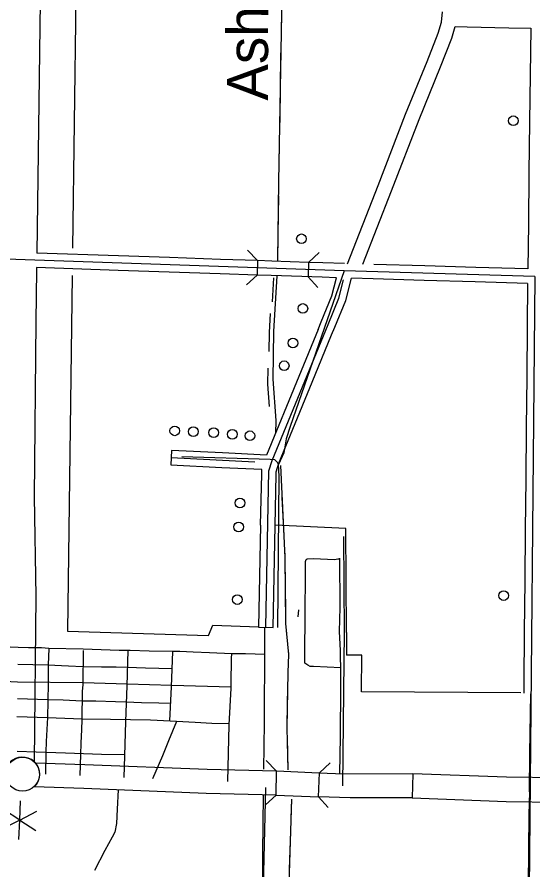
# Model space of a CAD drawing. Extents: x -4306 to 3843, y 131 to 8053.
# Drawn here: x 589 to 1443, y 3441 to 4853 of the extents above; entities that cross this region are included whole.
import ezdxf

# ---------------------------------------------------------------- set-up
doc = ezdxf.new("R2010")
doc.units = 0
for name, color, linetype in [('10', 7, 'Continuous'), ('24', 7, 'Continuous'), ('31', 7, 'Continuous'), ('32', 7, 'Continuous'), ('33', 7, 'Continuous'), ('34', 7, 'Continuous'), ('37', 7, 'Continuous'), ('38', 7, 'Continuous'), ('43', 7, 'Continuous'), ('46', 7, 'Continuous'), ('48', 7, 'Continuous'), ('56', 7, 'Continuous'), ('6', 7, 'Continuous')]:
    doc.layers.add(name, color=color, linetype=linetype)

msp = doc.modelspace()

# ---------------------------------------------------------------- linework, layer by layer
at = {"layer": '10'}
for p, q in [((1018.3, 3604.8), (1017.4, 3564.8)), ((1018.8, 3604.8), (1019.4, 3604.8)), ((1019.4, 3604.8), (1088.9, 3601.8)), ((1088.1, 3561.8), (1089.8, 3601.7)), ((1244.5, 3599.9), (1243, 3559.9)), ((1244.5, 3599.9), (1243, 3559.9)), ((1018.2, 3564.8), (1087.9, 3561.8))]:
    msp.add_line(p, q, dxfattribs=at)
for points in [[(968.7, 5290.2), (692.8, 5302.6), (674.8, 5297.7), (651, 5282.1), (641.1, 5271.4), (634.9, 5260.6), (632.5, 5254), (621.8, 4462.2)], [(621.5, 4438.2), (621.4, 4434.2)], [(621.4, 4434.2), (620.3, 4349.1), (617.7, 4058.9)], [(617.7, 4058.9), (620.3, 3894), (617.5, 3620.2)], [(619.7, 3618.1), (701.5, 3615.5), (903.8, 3607.5), (1018.5, 3604.8)], [(1088.9, 3601.8), (1116.1, 3600.6)], [(1116.1, 3600.6), (1244.5, 3599.9)], [(1819.6, 3589.7), (1570.2, 3591.9), (1399.5, 3594.1), (1244.5, 3599.9)], [(1018.2, 3564.8), (1018.1, 3564.8), (902.5, 3567.5), (700, 3575.5), (617.3, 3578.2)], [(1140.7, 3560), (1087.9, 3561.8)], [(1243, 3559.9), (1140.7, 3560)], [(1243, 3559.9), (1398.5, 3554.1), (1569.7, 3551.9), (1817.9, 3549.8)]]:
    msp.add_lwpolyline(points, dxfattribs=at)
for centre, radius, start, end in [((598.1, 3598.2), 29.3, 48.5826, 134.7506), ((598.5, 3599.3), 28.3, 311.6906, 41.5462)]:
    msp.add_arc(centre, radius, start, end, dxfattribs=at)
at = {"layer": '24'}
msp.add_circle((598.4, 3599.4), 28, dxfattribs=at)
at = {"layer": '31'}
for p, q in [((1110.5, 4391.4), (1118.2, 4421.4)), ((1121.9, 4387.6), (1129.7, 4418)), ((1133.3, 4383.8), (1142.8, 4420.7)), ((1092.8, 4348.6), (1110.5, 4391.4)), ((1103.9, 4344), (1121.9, 4387.6)), ((1115, 4339.4), (1133.3, 4383.8)), ((1011.3, 4118.6), (1103.9, 4344)), ((1087.6, 4336), (1092.8, 4348.6)), ((1109.8, 4326.9), (1115, 4339.4)), ((1087.6, 4336), (1087.6, 4336)), ((1022.6, 4114.6), (1045.6, 4170.6)), ((844.7, 4135.6), (843.5, 4111.6)), ((844.1, 4123.6), (982.6, 4116.8)), ((1006.2, 4101.9), (1011.3, 4118.6)), ((1018.2, 4100), (1022.6, 4114.6)), ((994.1, 4096.2), (994.2, 4103.8)), ((1001, 3842.6), (1006.2, 4101.9)), ((1018.1, 4095.7), (1018.2, 4100)), ((992.4, 4011.8), (994.1, 4096.2)), ((1016.4, 4011.3), (1018.1, 4095.7)), ((1054.8, 3871.6), (1054, 3859.8)), ((989, 3842.8), (1012.9, 3842.3))]:
    msp.add_line(p, q, dxfattribs=at)
for points in [[(1087.6, 4336), (1055.5, 4257.9)], [(1077.7, 4248.7), (1109.8, 4326.9)], [(1055.5, 4257.9), (1002.1, 4127.9)], [(1045.6, 4170.6), (1077.7, 4248.7)], [(929.1, 4131.5), (844.7, 4135.6)], [(1002.1, 4127.9), (929.1, 4131.5)], [(843.5, 4111.6), (927.9, 4107.5)], [(927.9, 4107.5), (994.3, 4104.3)], [(992.4, 4011.8), (990.7, 3927.3)], [(1014.7, 3926.8), (1016.4, 4011.3)], [(990.7, 3927.3), (989, 3842.8)], [(1012.9, 3842.3), (1014.7, 3926.8)]]:
    msp.add_lwpolyline(points, dxfattribs=at)
at = {"layer": '32'}
for p, q in [((1439.6, 4834.8), (1437.6, 4679.9)), ((1437.6, 4679.9), (1436.5, 4595.5)), ((1436.5, 4595.5), (1435.5, 4511)), ((1435.5, 4511), (1434.5, 4436.2)), ((602.5, 4450.9), (-239.3, 4486.5)), ((1130.8, 4433), (602.5, 4450.9)), ((757.3, 4457.6), (621.8, 4462.2)), ((841.8, 4454.8), (757.3, 4457.6)), ((926.2, 4451.9), (841.8, 4454.8)), ((987.3, 4449.9), (926.2, 4451.9)), ((987.3, 4449.9), (986.5, 4425.9)), ((1010.7, 4449.1), (987.3, 4449.9)), ((756.5, 4433.6), (621.5, 4438.2)), ((1071.7, 4447), (1010.7, 4449.1)), ((1071.8, 4447), (1071, 4423)), ((1095.1, 4446.2), (1071.8, 4447)), ((1131.2, 4445), (1095.1, 4446.2)), ((1263.9, 4441.1), (1179.5, 4443.6)), ((1348.4, 4438.7), (1263.9, 4441.1)), ((1434.5, 4436.2), (1348.4, 4438.7)), ((841, 4430.8), (756.5, 4433.6)), ((925.4, 4427.9), (841, 4430.8)), ((986.5, 4425.9), (925.4, 4427.9)), ((1009.9, 4425.1), (986.5, 4425.9)), ((1094.3, 4422.2), (1009.9, 4425.1)), ((1130.8, 4433), (1041.4, 4175.2)), ((1118.2, 4421.4), (1094.3, 4422.2)), ((1446.4, 4423.8), (1130.8, 4433)), ((1446.4, 4423.8), (1434.2, 3147)), ((1178.8, 4419.6), (1142.8, 4420.7)), ((1263.2, 4417.1), (1178.8, 4419.6)), ((1347.7, 4414.7), (1263.2, 4417.1)), ((1434.2, 4412.2), (1347.7, 4414.7)), ((1434.2, 4412.2), (1433.6, 4342)), ((1433.6, 4342), (1432.8, 4257.5)), ((1432.8, 4257.5), (1432, 4173)), ((1041.4, 4175.2), (1034.5, 4154.8)), ((1432, 4173), (1431.2, 4088.5)), ((1034.5, 4154.8), (1030.7, 4131.6)), ((1007.9, 4120.3), (862, 4124.7)), ((1030.7, 4131.6), (1021.8, 4112.2)), ((1016.1, 4120.1), (1007.9, 4120.3)), ((1020.2, 4115.4), (1016.1, 4120.1)), ((1021.8, 4112.2), (1020.2, 4115.4)), ((1023.3, 4093), (1021.8, 4112.2)), ((1020.6, 3842.1), (1023.3, 4093)), ((1431.2, 4088.5), (1430.4, 4004)), ((1430.4, 4004), (1429.5, 3919.5)), ((1429.5, 3919.5), (1428.7, 3835.1)), ((1428.7, 3835.1), (1427.9, 3750.6)), ((1427.9, 3750.6), (1427.8, 3733.7))]:
    msp.add_line(p, q, dxfattribs=at)
for points in [[(1129.5, 3992.9), (1130.7, 3833.8)], [(1130.7, 3833.8), (1129.6, 3736.4), (1127.8, 3580.1)], [(929.3, 3181.4), (991.6, 3178), (1001, 3577.3)]]:
    msp.add_lwpolyline(points, dxfattribs=at)
at = {"layer": '33'}
for p, q in [((1067.6, 3954.6), (1069.6, 3956)), ((1069.6, 3956), (1079.9, 3956.3)), ((1079.9, 3956.3), (1114.5, 3955)), ((1114.5, 3955), (1120.1, 3955.7)), ((1120.1, 3955.7), (1122.8, 3956)), ((1123.8, 3875.3), (1123.7, 3956.8)), ((1066.7, 3951.8), (1067.6, 3954.6)), ((1066.7, 3936.2), (1066.7, 3951.8)), ((1065.9, 3858.9), (1066.7, 3936.2)), ((1123, 3835.6), (1123.8, 3875.3)), ((1065.5, 3803), (1065.9, 3858.9)), ((999.4, 3775.4), (999.4, 3841.3)), ((1124.5, 3804.4), (1123, 3835.6)), ((591.3, 3809), (564.4, 3810.1)), ((608.1, 3808.4), (591.3, 3809)), ((629.5, 3808.6), (608.1, 3808.4)), ((641.7, 3807.3), (629.5, 3808.6)), ((641.7, 3807.3), (640.5, 3780.5)), ((698.5, 3806.3), (641.7, 3807.3)), ((698.4, 3747.7), (699.2, 3804)), ((758.3, 3804.4), (698.5, 3806.3)), ((773.3, 3803.9), (758.3, 3804.4)), ((771.6, 3745.4), (773.2, 3803.9)), ((776.7, 3804.2), (773.3, 3803.9)), ((808, 3803), (776.7, 3804.2)), ((846.2, 3802.4), (808, 3803)), ((845.1, 3743.7), (846.8, 3802.4)), ((858.4, 3802.3), (846.2, 3802.4)), ((880.5, 3801.2), (858.4, 3802.3)), ((907.5, 3800.1), (880.5, 3801.2)), ((944.9, 3798.8), (907.5, 3800.1)), ((1065.4, 3787.9), (1065.5, 3803)), ((1125.1, 3765.2), (1124.5, 3804.4)), ((943.7, 3748.7), (944.4, 3791.5)), ((944.4, 3791.5), (944.9, 3798.8)), ((967.4, 3798.5), (944.9, 3798.8)), ((999.4, 3797.7), (967.4, 3798.5)), ((1065.8, 3783.4), (1065.4, 3787.9)), ((590.7, 3781.3), (640.4, 3780.2)), ((640.4, 3780.2), (674.2, 3778.6)), ((640.5, 3780.5), (640.5, 3749.5)), ((674.2, 3778.6), (698.3, 3777.9)), ((698.3, 3777.9), (729.2, 3777)), ((729.2, 3777), (753.3, 3777.3)), ((753.3, 3777.3), (771.9, 3776.4)), ((771.9, 3776.4), (801.7, 3775.4)), ((801.7, 3775.4), (845.9, 3774.1)), ((999.4, 3758.1), (999.4, 3775.4)), ((1070.5, 3779.6), (1065.8, 3783.4)), ((1074.5, 3777.5), (1070.5, 3779.6)), ((1079.9, 3777.5), (1074.5, 3777.5)), ((1125, 3775.7), (1079.9, 3777.5)), ((999, 3738.5), (999.4, 3758.1)), ((1125.1, 3743.4), (1125.1, 3765.2)), ((590.2, 3751.8), (520, 3754.9)), ((698.6, 3750.7), (590.2, 3751.8)), ((640.5, 3749.5), (640.4, 3720.9)), ((697.3, 3736.3), (698.4, 3747.7)), ((771.7, 3748.3), (698.6, 3750.7)), ((769.4, 3686.8), (771.6, 3745.4)), ((845.2, 3746.1), (771.7, 3748.3)), ((842.2, 3687.8), (845.1, 3743.7)), ((943.6, 3743.5), (845.2, 3746.1)), ((943.6, 3741.6), (943.7, 3748.7)), ((1124.3, 3661.2), (1125.1, 3743.4)), ((696.9, 3689.1), (697.3, 3736.3)), ((940.3, 3681.3), (943.6, 3741.6)), ((999, 3722.6), (999, 3738.5)), ((1438.2, 3634.3), (1439.7, 3732.3)), ((589.9, 3724.6), (639.9, 3723.1)), ((640.4, 3720.9), (639.6, 3693.2)), ((639.9, 3723.1), (665.4, 3722.3)), ((665.4, 3722.3), (697, 3720.9)), ((697, 3720.9), (719.8, 3720.6)), ((719.8, 3720.6), (752.1, 3719.8)), ((752.1, 3719.8), (770, 3719.1)), ((770, 3719.1), (795.3, 3718.3)), ((795.3, 3718.3), (823.9, 3717.6)), ((823.9, 3717.6), (843.3, 3716.9)), ((998.9, 3685), (999, 3722.6)), ((589, 3694.9), (639.6, 3693.2)), ((639.6, 3693.2), (637.4, 3653.5)), ((639.6, 3693.2), (696.8, 3691.2)), ((696.5, 3673.5), (696.9, 3689.1)), ((696.8, 3691.2), (743.9, 3690.3)), ((743.9, 3690.3), (809.9, 3689.1)), ((767.8, 3629.6), (769.4, 3686.8)), ((809.9, 3689.1), (842.5, 3687.8)), ((840.6, 3655), (853.8, 3687.2)), ((842.5, 3687.8), (852.9, 3687.3)), ((852.9, 3687.3), (883.8, 3685.2)), ((695.1, 3650.8), (696.5, 3673.5)), ((883.8, 3685.2), (911.5, 3683.8)), ((911.5, 3683.8), (939.8, 3683)), ((938.1, 3587.4), (940.3, 3681.3)), ((998.5, 3645.2), (998.9, 3685)), ((1123.2, 3600.5), (1124.3, 3661.2)), ((637.4, 3653.5), (637.1, 3635.7)), ((694.7, 3632.1), (695.1, 3650.8)), ((830.5, 3630.4), (840.6, 3655)), ((997.9, 3607.7), (998.5, 3645.2)), ((589.5, 3637.2), (620.7, 3636.5)), ((620.7, 3636.5), (669.7, 3634.7)), ((637.1, 3635.7), (636.2, 3599.5)), ((669.7, 3634.7), (728.9, 3632.6)), ((693.6, 3597.2), (694.7, 3632.1)), ((728.9, 3632.6), (767.7, 3631.9)), ((814.1, 3592), (830.5, 3630.4)), ((1437.5, 3570.3), (1438.2, 3634.3)), ((766.4, 3594), (767.8, 3629.6)), ((756.4, 3573.3), (754.8, 3541.2)), ((996.6, 3565.6), (995.9, 3516.2)), ((754.8, 3541.2), (753.6, 3517.9)), ((753.6, 3517.9), (751, 3503.4)), ((751, 3503.4), (746.7, 3494.9)), ((995.9, 3516.2), (995.7, 3469.1)), ((746.7, 3494.9), (734.6, 3472.7)), ((734.6, 3472.7), (717.4, 3439.8)), ((995.7, 3469.1), (995.3, 3422.6))]:
    msp.add_line(p, q, dxfattribs=at)
at = {"layer": '34'}
for p, q in [((1437.5, 3570.3), (1436.5, 3532.3)), ((1436.5, 3532.3), (1434.9, 3415.7))]:
    msp.add_line(p, q, dxfattribs=at)
at = {"layer": '37'}
for p, q in [((1018.3, 3604.8), (1001.8, 3622.2)), ((1107.5, 3617.9), (1089.8, 3601.7)), ((1088.9, 3581.7), (1088.9, 3581.7)), ((1018.1, 3564.8), (1000.4, 3548.6)), ((1088.1, 3561.8), (1104.3, 3544.1))]:
    msp.add_line(p, q, dxfattribs=at)
at = {"layer": '38'}
for points in [[(970.9, 4467.4), (987.3, 4449.9)], [(1071.8, 4447), (1089.3, 4463.4)], [(986.5, 4425.9), (969, 4409.5)], [(1087.3, 4405.5), (1071, 4423)]]:
    msp.add_lwpolyline(points, dxfattribs=at)
at = {"layer": '43'}
for points in [[(1017.4, 5282.9), (1025.1, 5269.5), (1029.4, 5258.2), (1029.6, 5234.1), (1027.7, 5087.5), (1026.4, 4887), (1026.8, 4858.6), (1022.2, 4580.9), (1020.1, 4448.8)], [(1026.4, 4895), (1026.4, 4887), (1026.8, 4858.6), (1026.3, 4831.6)], [(1026, 4810.5), (1025.5, 4778.8)], [(1025.5, 4778.8), (1024.9, 4747.1)], [(1024.6, 4726), (1023.5, 4662.7)], [(1023.2, 4641.5), (1022.2, 4580.9), (1022.1, 4578.2)], [(1021.8, 4557.1), (1020.8, 4493.7)], [(1020.4, 4472.6), (1020.1, 4448.8)], [(1011.8, 4381.5), (1014.2, 4421.3)], [(1017.7, 4163.5), (1017.9, 4185.3), (1013.1, 4253.3), (1014.4, 4332.2), (1020, 4424.8)], [(1006.4, 4299.1), (1006.9, 4330.7), (1008.8, 4362.4)], [(1007, 4208.2), (1004.3, 4245.4), (1004.8, 4271.5)], [(1025, 4110.5), (1032.7, 3957.9), (1033.8, 3848.9), (1038.4, 3797.4)], [(1027.7, 4057.7), (1030.9, 3994.4)], [(1031.9, 3973.3), (1032.7, 3957.9), (1033.2, 3910)], [(1033.4, 3888.9), (1033.8, 3848.9), (1035.9, 3825.6)], [(1037.8, 3804.6), (1038.4, 3797.4)], [(1038.4, 3797.4), (1037.5, 3767.8), (1035.9, 3676.2), (1037.4, 3606.7)], [(1038.4, 3797.4), (1037.5, 3767.8), (1037.5, 3765.7)], [(1037.1, 3744.6), (1036, 3681.3)], [(1036.2, 3660.1), (1037.4, 3606.7)], [(1043.4, 3557.7), (1031.8, 3189.6)], [(1043.4, 3557.7), (1042.4, 3526.1)], [(1041.7, 3504.9), (1039.7, 3441.6)]]:
    msp.add_lwpolyline(points, dxfattribs=at)
at = {"layer": '46'}
for p, q in [((1291.7, 4844.6), (1293.3, 4862)), ((1286.1, 4826.4), (1291.7, 4844.6)), ((1308.8, 4818.5), (1314.6, 4837.4)), ((1314.6, 4837.4), (1334.2, 4836.9)), ((1334.2, 4836.9), (1402.9, 4835.2)), ((1402.9, 4835.2), (1439.6, 4834.8)), ((1268, 4779.8), (1286.1, 4826.4)), ((1290.3, 4770.9), (1308.8, 4818.5)), ((1232.4, 4692.3), (1268, 4779.8)), ((1254.7, 4683.5), (1290.3, 4770.9)), ((1186.8, 4574.3), (1232.4, 4692.3)), ((1209.1, 4565.6), (1254.7, 4683.5)), ((1136.3, 4444.8), (1186.8, 4574.3)), ((1161.8, 4444.1), (1209.1, 4565.6))]:
    msp.add_line(p, q, dxfattribs=at)
at = {"layer": '48'}
for p, q in [((593.6, 3523.3), (595.1, 3555.2)), ((593.6, 3523.3), (566.7, 3540.6)), ((593.6, 3523.3), (622, 3537.9)), ((593.6, 3523.3), (565.1, 3508.6)), ((592, 3491.3), (593.6, 3523.3)), ((593.6, 3523.3), (620.5, 3505.9))]:
    msp.add_line(p, q, dxfattribs=at)
at = {"layer": '56'}
for centre in [(1410.7, 4681.5), (1060, 4486), (1062.3, 4370.6), (1045.8, 4313.4), (1031.4, 4275.7), (850.3, 4167.9), (881.1, 4166.7), (914.7, 4165), (945.5, 4162.2), (974.6, 4159.8), (958.1, 4048.5), (956.1, 4008.8), (1394.7, 3895.1), (953.7, 3888.5)]:
    msp.add_circle(centre, 8, dxfattribs=at)
at = {"layer": '6'}
for p, q in [((691.9, 5319.8), (680.9, 4470.6)), ((680.3, 4425.2), (672.7, 3836.4)), ((1133.4, 4006), (1016.4, 4011.7))]:
    msp.add_line(p, q, dxfattribs=at)
for points in [[(1134.7, 3833.8), (1133.4, 4006)], [(672.7, 3836.4), (906.3, 3829), (913.3, 3845.9), (989, 3843.2)], [(1134.7, 3833.8), (1134.3, 3796.3)], [(1159.6, 3735.8), (1160.1, 3796.4), (1134.3, 3796.3)], [(1423, 3733.8), (1159.6, 3735.8)]]:
    msp.add_lwpolyline(points, dxfattribs=at)

# ---------------------------------------------------------------- texts
at = {"layer": '43'}
msp.add_text('Asher', height=67.59, rotation=89.7677, dxfattribs=at).set_placement((1004.3, 4715))

doc.saveas('drawing.dxf')
